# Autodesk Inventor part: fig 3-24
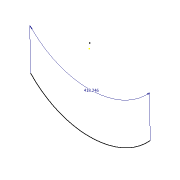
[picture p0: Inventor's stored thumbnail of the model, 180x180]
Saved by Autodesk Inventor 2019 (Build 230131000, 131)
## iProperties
Created: 2018-03
Part Number: fig 3-24
Material: Generic
Document SubType Name: Modeling
Designer: CADCIM 00
Density: 1 g/cm^3
Appearance: Default
Author: CADCIM 00
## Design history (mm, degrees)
sketch "Sketch1"
  geometry: A1 r 252.126 centre (0.845, 16.069) between (-182.963, -156.507) and (188.92, -151.846); 1 further point
  constraints: 2 point on circle, 1 centre point
  dimensions: "d0" = 418.246 dimension on point (0, 0) A1.start A1.end A1.centre A1; "d0" = 418.246 dimension on A1
